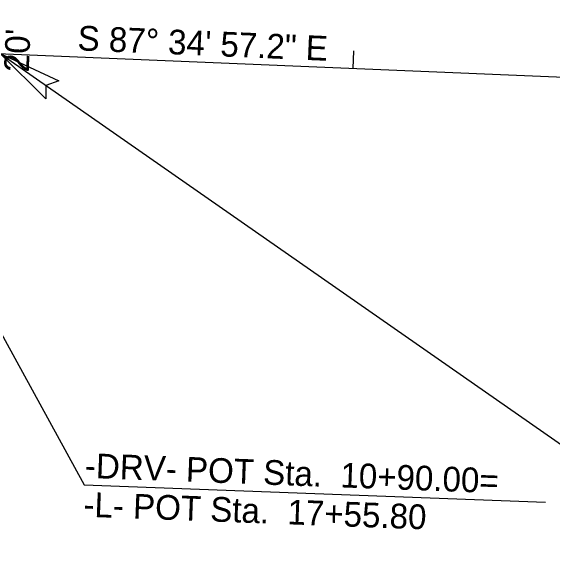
# Model space of a CAD drawing. Extents: x 2170295 to 2171718, y 723585 to 724580.
# Drawn here: x 2171203.6 to 2171356.7, y 723922.2 to 724074.8 of the extents above; entities that cross this region are included whole.
import ezdxf

# ---------------------------------------------------------------- set-up
doc = ezdxf.new("R2010")
doc.units = 0
for name, color, linetype in [('Prop Dimension', 7, 'Continuous'), ('Prop DSN Text', 7, 'Continuous'), ('Prop Horizontal Alignment', 7, 'Continuous'), ('Prop Horizontal Alignment Direction Label', 7, 'Continuous'), ('Prop Horizontal Alignment Station Label', 7, 'Continuous'), ('Prop Horizontal Alignment Tick Small', 7, 'Continuous'), ('Prop Terminator CELL', 7, 'Continuous')]:
    doc.layers.add(name, color=color, linetype=linetype)

msp = doc.modelspace()

# ---------------------------------------------------------------- linework, layer by layer
at = {"layer": 'Prop Dimension'}
msp.add_line((2171200.54, 724062.74), (2171439.97, 723895.67), dxfattribs=at)
at = {"layer": 'Prop Horizontal Alignment'}
msp.add_line((2170914.62, 724074.81), (2171360.17, 724056), dxfattribs=at)
at = {"layer": 'Prop Horizontal Alignment Station Label'}
for p, q in [((2171156.38, 724064.6), (2171224.4, 723940.64)), ((2171224.4, 723940.64), (2171354.77, 723935.76))]:
    msp.add_line(p, q, dxfattribs=at)
at = {"layer": 'Prop Horizontal Alignment Tick Small'}
msp.add_line((2171300.45, 724058.52), (2171300.66, 724063.51), dxfattribs=at)
at = {"layer": 'Prop Terminator CELL'}
msp.add_lwpolyline([(2171213.53, 724049.89), (2171200.54, 724062.74), (2171217.22, 724055), (2171213.5, 724053.7)], close=True, dxfattribs=at)

# ---------------------------------------------------------------- texts
at = {"layer": 'Prop DSN Text'}
msp.add_text("20'", height=7, rotation=87.5825, dxfattribs=at).set_placement((2171208.69, 724057.32))
at = {"layer": 'Prop Horizontal Alignment Direction Label'}
msp.add_text('S 87%%d 34\' 57.2" E', height=7, rotation=357.5825, dxfattribs=at).set_placement((2171222.4, 724063.64))
at = {"layer": 'Prop Horizontal Alignment Station Label'}
for s, p in [('-DRV- POT Sta.  10+90.00=', (2171224.47, 723942.64)), ('-L- POT Sta.  17+55.80', (2171224.06, 723931.65))]:
    msp.add_text(s, height=7, rotation=357.8574, dxfattribs=at).set_placement(p)

doc.saveas('drawing.dxf')
